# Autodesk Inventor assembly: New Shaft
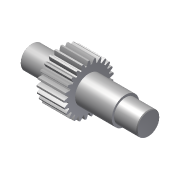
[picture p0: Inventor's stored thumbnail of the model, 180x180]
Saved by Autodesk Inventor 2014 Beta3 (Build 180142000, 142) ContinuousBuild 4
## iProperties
Created: 2011-01
Part Number: New Shaft
Document SubType Name: Assembly
Designer: Beta-8540w
ClientObjectVersion: 1
Author: Beta-8540w
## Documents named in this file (2)
- C:\Inventor 2014 Essentials\Assemblies\Chapter 09\Design Accelerators\Shaft c09-07.iam
- C:\Inventor 2014 Essentials\Assemblies\Chapter 09\Design Accelerators\Shaft c09-05.ipt
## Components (1 placed, 1 different names)
1. New Shaft:1
